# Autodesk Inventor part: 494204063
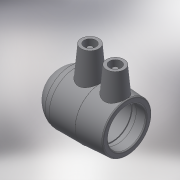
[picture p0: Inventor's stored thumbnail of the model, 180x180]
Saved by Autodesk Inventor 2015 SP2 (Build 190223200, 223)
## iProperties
Created: 2017-06
Part Number: 494204063
Material: Generic
Description: PLASSON END CAP MONOLITHIC 63
Document SubType Name: Modeling
Designer: Кирилл
Density: 1 g/cm^3
Appearance: Default
Author: Кирилл
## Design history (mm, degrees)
derived "494204.ipt"
feature "Solid1::494204.ipt"
tag "TaggingFeature1"
body "Solid1"
other parameters: "d0" = 95, "d1" = 1, "d2" = 62, "d3" = 63, "d4" = 81, "d5" = 9.5, "d7" = 2.43, "d8" = 33.25, "d10" = 1.62, "d11" = 19, "d12" = 168 deg, "d13" = 6.33333, "d14" = 63, "d15" = 62, "d16" = 15, "d17" = 47.5, "d18" = 1, "d20" = 5 deg, "d21" = 55.8, "d22" = 15, "d23" = 1, "d24" = 79.8, "d26" = 5 deg, "d27" = 4, "d29" = 14, "d30" = 0, "d31" = 4, "d33" = 14, "d34" = 0, "d37" = 56.7, "d38" = 62, "d39" = 71.3, "d40" = 64.8, "d41" = 3.15, "d42" = 0, "d44" = 360 deg, "d46" = 3, "d47" = 0, "d48" = 3, "d49" = 0, "d_" = 63, "L_" = 95, "L_1" = 62, "D_" = 81, "A_" = 62, "d_2" = 12
